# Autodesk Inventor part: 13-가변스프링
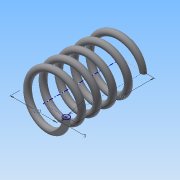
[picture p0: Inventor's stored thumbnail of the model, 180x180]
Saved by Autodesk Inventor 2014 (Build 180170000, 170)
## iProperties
Created: 2015-09
Part Number: 13-가변스프링
Material: 강철, 탄소
Document SubType Name: Modeling
Designer: study
Density: 1 g/cm^3
Appearance: 반연마
Author: study
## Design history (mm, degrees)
sketch "스케치1"
  geometry: L1 (0, 0)-(11, 0); L2 (11, 0)-(11, 36.261); L3 (11, 36.261)-(0, 36.261); L4 (0, 36.261)-(0, 0); C1 r 1.5 at (11, 0)
  constraints: 8 end point, 2 parallel, 1 centre point, 1 coincident, 1 horizontal, 1 perpendicular
  dimensions: "d0" = 3 diameter of C1; "d1" = 22 diameter of L1.end L4; "d2" = 36.2612 distance of L1.end L2.end (derived)
feature "코일1" sketch "스케치1" pitch "d3" = 10; turns "d5" = 5; dims "d4" = 36.2612 (= d2), "d6" = 0, angle "d7" = 90 deg, angle "d8" = 90 deg, "d9" = 0, "d10" = 0
node "작업 평면1"
sketch "스케치2"
  geometry: L1 (-12.5, 0)-(-9.5, 0) reference; 1 further point
  constraints: 1 horizontal alignment
extrude "돌출1" cut sketch "스케치2" stored distance "d12" = 10; taper "d13" = 0 deg
node "작업 평면2"
sketch "스케치3"
  geometry: L1 (-9.5, 0)-(-12.5, 0) reference; 1 further point
  constraints: 1 horizontal alignment
extrude "돌출2" cut sketch "스케치3" stored distance "d15" = 10; taper "d16" = 0 deg
node "솔리드1"
node "절단 모서리 투영1"
node "절단 모서리 투영2"
other parameters: "d11" = 0, "d14" = 36.2612 (= d2)
